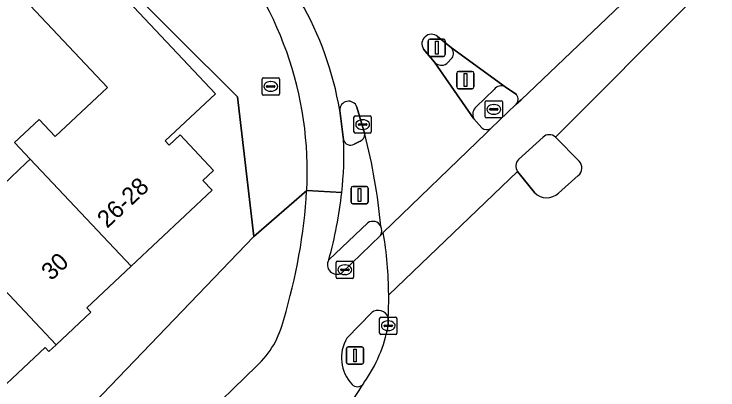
# Model space of a CAD drawing. Extents: x 162073 to 163043, y 381818 to 382561.
# Drawn here: x 162751.94 to 162792.63, y 382047.07 to 382068.82 of the extents above; entities that cross this region are included whole.
import ezdxf

# ---------------------------------------------------------------- set-up
doc = ezdxf.new("R2010")
doc.units = 0
for name, color, linetype in [('IMGEO_Brandkraan', 7, 'Continuous'), ('IMGEO_Erf', 7, 'Continuous'), ('IMGEO_Fietspad_gesloten', 7, 'Continuous'), ('IMGEO_Fietspad_open', 7, 'Continuous'), ('IMGEO_Kolk', 7, 'Continuous'), ('IMGEO_Lichtmast', 7, 'Continuous'), ('IMGEO_Pand', 7, 'Continuous'), ('IMGEO_Pand_nummerreeks', 7, 'Continuous'), ('IMGEO_Rijbaan_lokaal_gesloten', 7, 'Continuous'), ('IMGEO_Rijbaan_lokaal_open', 7, 'Continuous'), ('IMGEO_Rijbaan_regionaal_gesloten', 7, 'Continuous'), ('IMGEO_Rioolput', 7, 'Continuous'), ('IMGEO_Verkeerseiland_gesloten', 7, 'Continuous'), ('IMGEO_Verkeersregelinstallatiepaal', 7, 'Continuous'), ('IMGEO_Voetpad_open', 7, 'Continuous')]:
    doc.layers.add(name, color=color, linetype=linetype)

msp = doc.modelspace()

# ---------------------------------------------------------------- linework, layer by layer
at = {"layer": 'IMGEO_Brandkraan'}
for p, q in [((162766.275, 382064.209), (162766.275, 382065.061)), ((162766.35, 382065.135), (162767.202, 382065.135)), ((162767.276, 382065.061), (162767.276, 382064.209)), ((162766.534, 382064.629), (162766.534, 382064.641)), ((162766.577, 382064.678), (162766.975, 382064.678)), ((162766.763, 382064.915), (162766.788, 382064.915)), ((162767.018, 382064.641), (162767.018, 382064.629)), ((162766.972, 382064.592), (162766.574, 382064.592)), ((162766.786, 382064.355), (162766.761, 382064.355)), ((162767.202, 382064.135), (162766.35, 382064.135))]:
    msp.add_line(p, q, dxfattribs=at)
for points in [[(162766.275, 382064.209), (162766.275, 382065.061)], [(162766.35, 382065.135), (162767.202, 382065.135)], [(162767.276, 382065.061), (162767.276, 382064.209)], [(162767.202, 382064.135), (162766.35, 382064.135)]]:
    msp.add_lwpolyline(points, dxfattribs=at)
for centre, radius, start, end in [((162766.352, 382065.059), 0.0765, 91.552, 178.448), ((162766.352, 382065.059), 0.0765, 91.552, 178.448), ((162767.2, 382065.059), 0.0765, 1.552, 88.448), ((162767.2, 382065.059), 0.0765, 1.552, 88.448), ((162766.574, 382064.638), 0.0403, 85.8775, 175.7526), ((162766.571, 382064.628), 0.0366, 178.938, 274.7102), ((162766.975, 382064.635), 0.043, 264.8664, 352.4533), ((162766.979, 382064.64), 0.0386, 1.7309, 96.639), ((162766.352, 382064.211), 0.0765, 181.552, 268.448), ((162766.352, 382064.211), 0.0765, 181.552, 268.448), ((162767.2, 382064.211), 0.0765, 271.552, 358.448), ((162767.2, 382064.211), 0.0765, 271.552, 358.448)]:
    msp.add_arc(centre, radius, start, end, dxfattribs=at)
for centre, major_axis, ratio, start_param, end_param in [((162766.762, 382064.635), (-0.387, 0.002), 0.722429, 4.712389, 7.853982), ((162766.787, 382064.635), (-0.39, 0.002), 0.717154, 1.570796, 4.712389)]:
    msp.add_ellipse(centre, major_axis=major_axis, ratio=ratio, start_param=start_param, end_param=end_param, dxfattribs=at)
at = {"layer": 'IMGEO_Erf'}
for points in [[(162765.79, 382055.945), (162764.864, 382064.031), (162750.594, 382078.24)], [(162756.005, 382072.267), (162763.573, 382064.216), (162760.672, 382061.489), (162760.905, 382061.242), (162761.532, 382061.832), (162763.464, 382059.778), (162762.847, 382059.198), (162763.381, 382058.631), (162758.701, 382054.231), (162756.144, 382051.827), (162756.382, 382051.575), (162754.366, 382049.68), (162753.955, 382049.294), (162753.729, 382049.534), (162749.568, 382045.622)], [(162750.844, 382058.524), (162752.637, 382060.209), (162752.868, 382060.426), (162751.964, 382061.386), (162753.385, 382062.722), (162754.313, 382061.735), (162757.336, 382064.577), (162752.874, 382069.324)], [(162724.511, 382016.802), (162741.397, 382032.094), (162754.763, 382044.439), (162765.79, 382055.945)]]:
    msp.add_lwpolyline(points, dxfattribs=at)
at = {"layer": 'IMGEO_Fietspad_gesloten'}
for points in [[(162770.981, 382061.536), (162770.765, 382063.245)], [(162768.854, 382058.613), (162770.878, 382058.5)]]:
    msp.add_lwpolyline(points, dxfattribs=at)
for centre, radius, start, end in [((162752.178, 382060.128), 18.847, 9.5189, 50.5147), ((162748.292, 382059.746), 20.593, 356.8466, 42.2355), ((162753.635, 382060.605), 17.371, 353.0408, 3.073)]:
    msp.add_arc(centre, radius, start, end, dxfattribs=at)
at = {"layer": 'IMGEO_Fietspad_open'}
for points in [[(162770.878, 382058.5), (162768.854, 382058.613)], [(162773.283, 382056.18), (162773.114, 382056.016), (162770.889, 382053.84)], [(162771.185, 382050.076), (162772.617, 382051.559)], [(162765.967, 382048.461), (162762.552, 382045.151), (162756.804, 382039.587), (162754.646, 382037.542), (162752.404, 382035.511), (162744.085, 382028.233), (162756.358, 382034.471)]]:
    msp.add_lwpolyline(points, dxfattribs=at)
for centre, radius, start, end in [((162736.765, 382060.483), 32.143, 343.1291, 356.6657), ((162747.002, 382061.053), 24.012, 344.4305, 353.8968), ((162750.411, 382052.365), 23.188, 0.542, 9.4704), ((162770.608, 382054.32), 0.556, 148.7674, 300.3303), ((162749.27, 382052.382), 24.328, 357.4107, 0.4756), ((162772.982, 382051.028), 0.645, 23.332, 124.4927), ((162762.356, 382052.347), 5.305, 312.8986, 346.9995), ((162773.082, 382048.928), 2.217, 148.8157, 223.7802), ((162747.331, 382062.556), 29.052, 321.7942, 328.5794), ((162771.795, 382047.681), 0.425, 222.4533, 320.5804)]:
    msp.add_arc(centre, radius, start, end, dxfattribs=at)
at = {"layer": 'IMGEO_Kolk'}
for p, q in [((162771.589, 382062.002), (162771.589, 382062.854)), ((162771.664, 382062.928), (162772.516, 382062.928)), ((162772.077, 382062.708), (162772.102, 382062.708)), ((162772.59, 382062.854), (162772.59, 382062.002)), ((162771.848, 382062.422), (162771.848, 382062.434)), ((162772.286, 382062.385), (162771.888, 382062.385)), ((162771.891, 382062.471), (162772.289, 382062.471)), ((162772.332, 382062.434), (162772.332, 382062.422)), ((162772.516, 382061.928), (162771.664, 382061.928)), ((162772.1, 382062.148), (162772.075, 382062.148)), ((162770.564, 382053.6), (162770.564, 382054.452)), ((162770.639, 382054.526), (162771.491, 382054.526)), ((162771.565, 382054.452), (162771.565, 382053.6)), ((162770.823, 382054.02), (162770.823, 382054.032)), ((162770.866, 382054.069), (162771.264, 382054.069)), ((162771.052, 382054.306), (162771.077, 382054.306)), ((162771.307, 382054.032), (162771.307, 382054.02)), ((162771.261, 382053.983), (162770.863, 382053.983)), ((162771.075, 382053.746), (162771.05, 382053.746)), ((162771.491, 382053.526), (162770.639, 382053.526)), ((162773.072, 382050.36), (162773.072, 382051.212)), ((162773.147, 382051.286), (162773.999, 382051.286)), ((162774.073, 382051.212), (162774.073, 382050.36)), ((162773.331, 382050.78), (162773.331, 382050.792)), ((162773.374, 382050.829), (162773.772, 382050.829)), ((162773.56, 382051.066), (162773.585, 382051.066)), ((162773.815, 382050.792), (162773.815, 382050.78)), ((162773.769, 382050.743), (162773.371, 382050.743)), ((162773.583, 382050.506), (162773.558, 382050.506)), ((162773.999, 382050.286), (162773.147, 382050.286))]:
    msp.add_line(p, q, dxfattribs=at)
for points in [[(162771.589, 382062.002), (162771.589, 382062.854)], [(162771.664, 382062.928), (162772.516, 382062.928)], [(162772.59, 382062.854), (162772.59, 382062.002)], [(162772.516, 382061.928), (162771.664, 382061.928)], [(162770.564, 382053.6), (162770.564, 382054.452)], [(162770.639, 382054.526), (162771.491, 382054.526)], [(162771.565, 382054.452), (162771.565, 382053.6)], [(162771.491, 382053.526), (162770.639, 382053.526)], [(162773.072, 382050.36), (162773.072, 382051.212)], [(162773.147, 382051.286), (162773.999, 382051.286)], [(162774.073, 382051.212), (162774.073, 382050.36)], [(162773.999, 382050.286), (162773.147, 382050.286)]]:
    msp.add_lwpolyline(points, dxfattribs=at)
for centre, radius, start, end in [((162771.666, 382062.852), 0.0765, 91.552, 178.448), ((162771.666, 382062.852), 0.0765, 91.552, 178.448), ((162772.514, 382062.852), 0.0765, 1.552, 88.448), ((162772.514, 382062.852), 0.0765, 1.552, 88.448), ((162771.888, 382062.431), 0.0403, 85.8775, 175.7526), ((162771.885, 382062.421), 0.0366, 178.938, 274.7102), ((162772.289, 382062.428), 0.043, 264.8664, 352.4533), ((162772.293, 382062.433), 0.0386, 1.7309, 96.639), ((162771.666, 382062.004), 0.0765, 181.552, 268.448), ((162771.666, 382062.004), 0.0765, 181.552, 268.448), ((162772.514, 382062.004), 0.0765, 271.552, 358.448), ((162772.514, 382062.004), 0.0765, 271.552, 358.448), ((162770.641, 382054.45), 0.0765, 91.552, 178.448), ((162770.641, 382054.45), 0.0765, 91.552, 178.448), ((162771.489, 382054.45), 0.0765, 1.552, 88.448), ((162771.489, 382054.45), 0.0765, 1.552, 88.448), ((162770.863, 382054.029), 0.0403, 85.8775, 175.7526), ((162771.268, 382054.031), 0.0386, 1.7309, 96.639), ((162770.86, 382054.019), 0.0366, 178.938, 274.7102), ((162771.264, 382054.026), 0.043, 264.8664, 352.4533), ((162770.641, 382053.602), 0.0765, 181.552, 268.448), ((162770.641, 382053.602), 0.0765, 181.552, 268.448), ((162771.489, 382053.602), 0.0765, 271.552, 358.448), ((162771.489, 382053.602), 0.0765, 271.552, 358.448), ((162773.149, 382051.21), 0.0765, 91.552, 178.448), ((162773.149, 382051.21), 0.0765, 91.552, 178.448), ((162773.997, 382051.21), 0.0765, 1.552, 88.448), ((162773.997, 382051.21), 0.0765, 1.552, 88.448), ((162773.371, 382050.789), 0.0403, 85.8775, 175.7526), ((162773.368, 382050.779), 0.0366, 178.938, 274.7102), ((162773.772, 382050.786), 0.043, 264.8664, 352.4533), ((162773.776, 382050.791), 0.0386, 1.7309, 96.639), ((162773.149, 382050.362), 0.0765, 181.552, 268.448), ((162773.149, 382050.362), 0.0765, 181.552, 268.448), ((162773.997, 382050.362), 0.0765, 271.552, 358.448), ((162773.997, 382050.362), 0.0765, 271.552, 358.448)]:
    msp.add_arc(centre, radius, start, end, dxfattribs=at)
for centre, major_axis, ratio, start_param, end_param in [((162772.076, 382062.428), (-0.387, 0.002), 0.722429, 4.712389, 7.853982), ((162772.101, 382062.428), (-0.39, 0.002), 0.717154, 1.570796, 4.712389), ((162771.051, 382054.026), (-0.387, 0.002), 0.722429, 4.712389, 7.853982), ((162771.076, 382054.026), (-0.39, 0.002), 0.717154, 1.570796, 4.712389), ((162773.559, 382050.786), (-0.387, 0.002), 0.722429, 4.712389, 7.853982), ((162773.584, 382050.786), (-0.39, 0.002), 0.717154, 1.570796, 4.712389)]:
    msp.add_ellipse(centre, major_axis=major_axis, ratio=ratio, start_param=start_param, end_param=end_param, dxfattribs=at)
at = {"layer": 'IMGEO_Lichtmast'}
for p, q in [((162775.879, 382066.475), (162775.879, 382067.275)), ((162775.879, 382067.275), (162775.879, 382066.475)), ((162775.979, 382067.375), (162776.769, 382067.375)), ((162776.769, 382067.375), (162775.979, 382067.375)), ((162776.869, 382067.275), (162776.869, 382066.475)), ((162776.869, 382066.475), (162776.869, 382067.275)), ((162776.769, 382066.375), (162775.979, 382066.375)), ((162775.979, 382066.375), (162776.769, 382066.375))]:
    msp.add_line(p, q, dxfattribs=at)
msp.add_lwpolyline([(162776.299, 382067.25), (162776.449, 382067.25), (162776.449, 382066.5), (162776.299, 382066.5), (162776.299, 382067.25)], dxfattribs=at)
for centre, start, end in [((162775.979, 382067.275), 90, 180), ((162775.979, 382067.275), 90, 180), ((162776.769, 382067.275), 0, 90), ((162776.769, 382067.275), 360, 90), ((162775.979, 382066.475), 180, 270), ((162775.979, 382066.475), 180, 270), ((162776.769, 382066.475), 270, 0), ((162776.769, 382066.475), 270, 0)]:
    msp.add_arc(centre, 0.1, start, end, dxfattribs=at)
at = {"layer": 'IMGEO_Pand'}
for points in [[(162763.573, 382064.216), (162756.005, 382072.267), (162752.874, 382069.324), (162757.336, 382064.577), (162754.313, 382061.735), (162753.385, 382062.722), (162751.964, 382061.386), (162752.868, 382060.426), (162758.701, 382054.231), (162763.381, 382058.631), (162762.847, 382059.198), (162763.464, 382059.778), (162761.532, 382061.832), (162760.905, 382061.242), (162760.672, 382061.489)], [(162752.868, 382060.426), (162752.637, 382060.209), (162750.844, 382058.524), (162750.134, 382057.856), (162749.056, 382058.583), (162747.499, 382057.119), (162748.291, 382056.132), (162754.366, 382049.68), (162756.382, 382051.575), (162756.144, 382051.827), (162758.701, 382054.231)], [(162754.366, 382049.68), (162748.291, 382056.132), (162745.685, 382053.681), (162744.57, 382054.365), (162743.029, 382052.915), (162743.914, 382051.974), (162743.74, 382051.811), (162749.568, 382045.622), (162753.729, 382049.534), (162753.955, 382049.294)]]:
    msp.add_lwpolyline(points, close=True, dxfattribs=at)
at = {"layer": 'IMGEO_Rijbaan_lokaal_gesloten'}
for points in [[(162783.235, 382061.7), (162791.215, 382069.716), (162789.352, 382069.377)], [(162787.03, 382069.371), (162781.257, 382063.867), (162780.954, 382063.58), (162779.502, 382062.202), (162779.227, 382061.936), (162773.283, 382056.18)], [(162781.102, 382060.41), (162782.523, 382061.7)], [(162773.598, 382052.584), (162781.047, 382059.707)]]:
    msp.add_lwpolyline(points, dxfattribs=at)
for centre, radius, start, end in [((162782.879, 382061.321), 0.52, 46.7862, 133.2138), ((162781.5, 382060.025), 0.553, 135.9492, 215.1039), ((162750.411, 382052.365), 23.188, 0.542, 9.4704)]:
    msp.add_arc(centre, radius, start, end, dxfattribs=at)
at = {"layer": 'IMGEO_Rijbaan_lokaal_open'}
for points in [[(162780.954, 382063.58), (162781.257, 382063.867), (162787.03, 382069.371), (162786.765, 382069.397), (162786.63, 382069.419), (162785.629, 382069.551)], [(162776.416, 382067.531), (162777.223, 382066.87), (162780.338, 382064.616), (162780.986, 382064.164)], [(162778.976, 382062.243), (162778.518, 382062.769), (162776.252, 382066.037), (162775.61, 382066.799)], [(162771.762, 382063.443), (162772.21, 382061.871)], [(162773.114, 382056.016), (162773.283, 382056.18), (162779.227, 382061.936), (162779.502, 382062.202)]]:
    msp.add_lwpolyline(points, dxfattribs=at)
for centre, radius, start, end in [((162752.178, 382060.128), 18.847, 9.5189, 50.5147), ((162776.069, 382067.103), 0.551, 50.9682, 213.5226), ((162780.633, 382063.89), 0.446, 315.9232, 37.8041), ((162771.279, 382063.266), 0.514, 20.0754, 182.3897), ((162779.266, 382062.564), 0.432, 227.955, 303.131), ((162741.449, 382053.787), 31.805, 4.9917, 14.7253), ((162772.672, 382056.302), 0.526, 327.1049, 28.6371)]:
    msp.add_arc(centre, radius, start, end, dxfattribs=at)
at = {"layer": 'IMGEO_Rijbaan_regionaal_gesloten'}
for points in [[(162807.056, 382061.983), (162807.554, 382062.355), (162809.533, 382063.835), (162810.384, 382064.471), (162813.682, 382066.937), (162811.272, 382069.185), (162808.646, 382071.634), (162806.458, 382073.675), (162804.04, 382075.93), (162799.744, 382073.158), (162799.619, 382073.087), (162799.428, 382072.978), (162796.25, 382071.3), (162792.509, 382069.951), (162791.215, 382069.716), (162783.235, 382061.7), (162784.601, 382060.305)], [(162782.031, 382058.491), (162781.047, 382059.707), (162773.598, 382052.584)], [(162784.558, 382059.487), (162783.417, 382058.461)], [(162773.574, 382051.283), (162773.573, 382050.786)], [(162772.186, 382047.515), (162772.123, 382047.411)]]:
    msp.add_lwpolyline(points, dxfattribs=at)
for centre, radius, start, end in [((162784.241, 382059.914), 0.531, 306.5833, 47.3985), ((162782.739, 382059.19), 0.995, 224.6168, 312.9032), ((162749.27, 382052.382), 24.328, 357.4107, 0.4756), ((162765.257, 382052.383), 8.468, 324.9123, 349.1309), ((162747.331, 382062.556), 29.052, 321.7942, 328.5794)]:
    msp.add_arc(centre, radius, start, end, dxfattribs=at)
at = {"layer": 'IMGEO_Rioolput'}
for p, q in [((162779.248, 382063.809), (162780.1, 382063.809)), ((162779.173, 382062.883), (162779.173, 382063.735)), ((162779.661, 382063.589), (162779.686, 382063.589)), ((162780.174, 382063.735), (162780.174, 382062.883)), ((162779.432, 382063.303), (162779.432, 382063.315)), ((162779.87, 382063.266), (162779.472, 382063.266)), ((162779.475, 382063.352), (162779.873, 382063.352)), ((162779.684, 382063.029), (162779.659, 382063.029)), ((162779.916, 382063.315), (162779.916, 382063.303)), ((162780.1, 382062.809), (162779.248, 382062.809))]:
    msp.add_line(p, q, dxfattribs=at)
for points in [[(162779.248, 382063.809), (162780.1, 382063.809)], [(162779.173, 382062.883), (162779.173, 382063.735)], [(162780.174, 382063.735), (162780.174, 382062.883)], [(162780.1, 382062.809), (162779.248, 382062.809)]]:
    msp.add_lwpolyline(points, dxfattribs=at)
for centre, radius, start, end in [((162779.25, 382063.733), 0.0765, 91.552, 178.448), ((162779.25, 382063.733), 0.0765, 91.552, 178.448), ((162780.098, 382063.733), 0.0765, 1.552, 88.448), ((162780.098, 382063.733), 0.0765, 1.552, 88.448), ((162779.472, 382063.312), 0.0403, 85.8775, 175.7526), ((162779.469, 382063.302), 0.0366, 178.938, 274.7102), ((162779.873, 382063.309), 0.043, 264.8664, 352.4533), ((162779.877, 382063.314), 0.0386, 1.7309, 96.639), ((162779.25, 382062.885), 0.0765, 181.552, 268.448), ((162779.25, 382062.885), 0.0765, 181.552, 268.448), ((162780.098, 382062.885), 0.0765, 271.552, 358.448), ((162780.098, 382062.885), 0.0765, 271.552, 358.448)]:
    msp.add_arc(centre, radius, start, end, dxfattribs=at)
for centre, major_axis, ratio, start_param, end_param in [((162779.66, 382063.309), (-0.387, 0.002), 0.722429, 4.712389, 7.853982), ((162779.685, 382063.309), (-0.39, 0.002), 0.717154, 1.570796, 4.712389)]:
    msp.add_ellipse(centre, major_axis=major_axis, ratio=ratio, start_param=start_param, end_param=end_param, dxfattribs=at)
at = {"layer": 'IMGEO_Verkeerseiland_gesloten'}
for points in [[(162777.223, 382066.87), (162776.416, 382067.531)], [(162775.61, 382066.799), (162776.252, 382066.037)], [(162776.952, 382065.957), (162777.265, 382066.286)], [(162780.986, 382064.164), (162780.338, 382064.616)], [(162779.701, 382064.464), (162778.663, 382063.461)], [(162772.21, 382061.871), (162771.762, 382063.443)], [(162779.502, 382062.202), (162780.954, 382063.58)], [(162770.765, 382063.245), (162770.981, 382061.536)], [(162778.518, 382062.769), (162778.976, 382062.243)], [(162771.593, 382061.303), (162771.956, 382061.473)], [(162782.523, 382061.7), (162781.102, 382060.41)], [(162784.601, 382060.305), (162783.235, 382061.7)], [(162781.047, 382059.707), (162782.031, 382058.491)], [(162783.417, 382058.461), (162784.558, 382059.487)], [(162772.399, 382056.75), (162770.133, 382054.608)], [(162770.889, 382053.84), (162773.114, 382056.016)], [(162772.617, 382051.559), (162771.185, 382050.076)], [(162773.573, 382050.786), (162773.574, 382051.283)], [(162772.123, 382047.411), (162772.186, 382047.515)]]:
    msp.add_lwpolyline(points, dxfattribs=at)
for centre, radius, start, end in [((162776.069, 382067.103), 0.551, 50.9682, 213.5226), ((162776.877, 382066.552), 0.47, 325.6117, 42.6153), ((162776.645, 382066.375), 0.519, 220.7156, 306.2448), ((162780.107, 382064.173), 0.499, 62.4394, 144.4023), ((162780.633, 382063.89), 0.446, 315.9232, 37.8041), ((162771.279, 382063.266), 0.514, 20.0754, 182.3897), ((162779.013, 382063.026), 0.558, 128.8717, 207.4595), ((162779.266, 382062.564), 0.432, 227.955, 303.131), ((162771.816, 382061.843), 0.395, 290.7857, 4.123), ((162782.879, 382061.321), 0.52, 46.7862, 133.2138), ((162771.376, 382061.653), 0.412, 196.4452, 301.8692), ((162781.5, 382060.025), 0.553, 135.9492, 215.1039), ((162784.241, 382059.914), 0.531, 306.5833, 47.3985), ((162782.739, 382059.19), 0.995, 224.6168, 312.9032), ((162772.674, 382056.304), 0.524, 28.5157, 121.6215), ((162772.672, 382056.302), 0.526, 327.1049, 28.6371), ((162770.608, 382054.32), 0.556, 148.7674, 300.3303), ((162772.982, 382051.028), 0.645, 23.332, 124.4927), ((162765.257, 382052.383), 8.468, 324.9123, 349.1309), ((162773.082, 382048.928), 2.217, 148.8157, 223.7802), ((162771.795, 382047.681), 0.425, 222.4533, 320.5804)]:
    msp.add_arc(centre, radius, start, end, dxfattribs=at)
at = {"layer": 'IMGEO_Verkeersregelinstallatiepaal'}
for p, q in [((162777.636, 382065.503), (162778.426, 382065.503)), ((162778.426, 382065.503), (162777.636, 382065.503)), ((162777.536, 382064.603), (162777.536, 382065.403)), ((162777.536, 382065.403), (162777.536, 382064.603)), ((162778.526, 382065.403), (162778.526, 382064.603)), ((162778.526, 382064.603), (162778.526, 382065.403)), ((162778.426, 382064.503), (162777.636, 382064.503)), ((162777.636, 382064.503), (162778.426, 382064.503)), ((162771.42, 382057.945), (162771.42, 382058.745)), ((162771.42, 382058.745), (162771.42, 382057.945)), ((162771.52, 382058.845), (162772.31, 382058.845)), ((162772.31, 382058.845), (162771.52, 382058.845)), ((162772.41, 382058.745), (162772.41, 382057.945)), ((162772.41, 382057.945), (162772.41, 382058.745)), ((162772.31, 382057.845), (162771.52, 382057.845)), ((162771.52, 382057.845), (162772.31, 382057.845)), ((162771.254, 382049.565), (162772.044, 382049.565)), ((162772.044, 382049.565), (162771.254, 382049.565)), ((162771.154, 382048.665), (162771.154, 382049.465)), ((162771.154, 382049.465), (162771.154, 382048.665)), ((162772.144, 382049.465), (162772.144, 382048.665)), ((162772.144, 382048.665), (162772.144, 382049.465)), ((162772.044, 382048.565), (162771.254, 382048.565)), ((162771.254, 382048.565), (162772.044, 382048.565))]:
    msp.add_line(p, q, dxfattribs=at)
for points in [[(162777.956, 382065.378), (162778.106, 382065.378), (162778.106, 382064.628), (162777.956, 382064.628), (162777.956, 382065.378)], [(162771.84, 382058.72), (162771.99, 382058.72), (162771.99, 382057.97), (162771.84, 382057.97), (162771.84, 382058.72)], [(162771.574, 382049.44), (162771.724, 382049.44), (162771.724, 382048.69), (162771.574, 382048.69), (162771.574, 382049.44)]]:
    msp.add_lwpolyline(points, dxfattribs=at)
for centre, start, end in [((162777.636, 382065.403), 90, 180), ((162777.636, 382065.403), 90, 180), ((162778.426, 382065.403), 0, 90), ((162778.426, 382065.403), 360, 90), ((162777.636, 382064.603), 180, 270), ((162777.636, 382064.603), 180, 270), ((162778.426, 382064.603), 270, 0), ((162778.426, 382064.603), 270, 0), ((162771.52, 382058.745), 90, 180), ((162771.52, 382058.745), 90, 180), ((162772.31, 382058.745), 0, 90), ((162772.31, 382058.745), 360, 90), ((162771.52, 382057.945), 180, 270), ((162771.52, 382057.945), 180, 270), ((162772.31, 382057.945), 270, 0), ((162772.31, 382057.945), 270, 0), ((162771.254, 382049.465), 90, 180), ((162771.254, 382049.465), 90, 180), ((162772.044, 382049.465), 0, 90), ((162772.044, 382049.465), 360, 90), ((162771.254, 382048.665), 180, 270), ((162771.254, 382048.665), 180, 270), ((162772.044, 382048.665), 270, 0), ((162772.044, 382048.665), 270, 0)]:
    msp.add_arc(centre, 0.1, start, end, dxfattribs=at)
at = {"layer": 'IMGEO_Voetpad_open'}
for points in [[(162652.011, 382165.5), (162668.909, 382150.217), (162670.073, 382149.164), (162674.032, 382145.847), (162749.277, 382079.405), (162750.581, 382078.253), (162750.594, 382078.24), (162764.864, 382064.031), (162765.79, 382055.945), (162768.854, 382058.613)], [(162780.338, 382064.616), (162777.223, 382066.87)], [(162777.265, 382066.286), (162776.952, 382065.957)], [(162776.252, 382066.037), (162778.518, 382062.769)], [(162778.663, 382063.461), (162779.701, 382064.464)], [(162771.956, 382061.473), (162771.593, 382061.303)], [(162768.854, 382058.613), (162765.79, 382055.945), (162754.763, 382044.439), (162741.397, 382032.094), (162724.511, 382016.802)], [(162770.133, 382054.608), (162772.399, 382056.75)], [(162752.404, 382035.511), (162754.646, 382037.542), (162756.804, 382039.587), (162762.552, 382045.151), (162765.967, 382048.461)]]:
    msp.add_lwpolyline(points, dxfattribs=at)
for centre, radius, start, end in [((162748.292, 382059.746), 20.593, 356.8466, 42.2355), ((162776.877, 382066.552), 0.47, 325.6117, 42.6153), ((162776.645, 382066.375), 0.519, 220.7156, 306.2448), ((162780.107, 382064.173), 0.499, 62.4394, 144.4023), ((162779.013, 382063.026), 0.558, 128.8717, 207.4595), ((162771.816, 382061.843), 0.395, 290.7857, 4.123), ((162741.449, 382053.787), 31.805, 4.9917, 14.7253), ((162753.635, 382060.605), 17.371, 353.0408, 3.073), ((162771.376, 382061.653), 0.412, 196.4452, 301.8692), ((162736.765, 382060.483), 32.143, 343.1291, 356.6657), ((162747.002, 382061.053), 24.012, 344.4305, 353.8968), ((162772.674, 382056.304), 0.524, 28.5157, 121.6215), ((162762.356, 382052.347), 5.305, 312.8986, 346.9995)]:
    msp.add_arc(centre, radius, start, end, dxfattribs=at)

# ---------------------------------------------------------------- texts
at = {"layer": 'IMGEO_Pand_nummerreeks'}
for s, rotation, p in [('26-28', 43.2354, (162757.317, 382056.388)), ('30', 43.2411, (162754.089, 382053.353))]:
    msp.add_text(s, height=1, rotation=rotation, dxfattribs=at).set_placement(p)

doc.saveas('drawing.dxf')
